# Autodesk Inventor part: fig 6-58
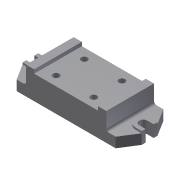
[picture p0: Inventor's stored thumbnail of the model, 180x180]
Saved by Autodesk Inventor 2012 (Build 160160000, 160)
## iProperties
Shininess: 77.0
Angle Display Precision: 2
Document Length Units: 11269
Document Angle Units: 11279
Document Time Units: 11290
Document Mass Units: 11283
Document Length Units Precision: 3
Document Angle Units Precision: 2
Created: 2001-12
Part Number: fig 6-58
Document SubType Name: Modeling
Designer: Renu Muthoo
Density: 1 g/cm^3
Material: Default
Density: 0.0
Volumn: 0.0
Area: 0.0
PropertySet Name: Model Information
Control State: 0
Master: False
Checked Out: False
Author: Renu Muthoo
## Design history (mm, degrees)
sketch "Sketch3"
  geometry: L1 (-59.119, -24.322)-(-59.119, 19.678); L2 (-59.119, 19.678)-(-46.119, 19.678); L3 (-46.119, 19.678)-(-46.119, 13.678); L4 (-46.119, 13.678)-(55.881, 13.678); L5 (55.881, 13.678)-(55.881, 19.678); L6 (55.881, 19.678)-(68.881, 19.678); L7 (68.881, 19.678)-(68.881, -24.322); L8 (68.881, -24.322)-(-59.119, -24.322)
  constraints: 16 end point, 2 equal length
  dimensions: "d10" = 13 distance of L1.end L2.end; "d11" = 102 distance of L3.end L4.end; "d13" = 44 distance between parallel lines of L2 L8; "d14" = 6 distance of L2.end L3.end
extrude "Extrusion1" new body sketch "Sketch3" distance "d15" = 76; taper "d16" = 0 deg
sketch "Sketch4"
  geometry: L1 (0, 0)-(0, 76) reference; L2 (0, 76)-(-15, 76); L3 (-15, 76)-(-31, 50.5); L4 (-31, 50.5)-(-31, 44.5); L5 (-31, 44.5)-(-21, 44.5); L6 (-21, 31.5)-(-31, 31.5); L7 (-31, 31.5)-(-31, 25.5); L8 (-31, 25.5)-(-15, 0); L9 (-15, 0)-(0, 0); L10 (128, 76)-(0, 76) reference; L11 (0, 0)-(128, 0) reference; A1 r 6.5 centre (-21, 38) between (-21, 31.5) and (-21, 44.5)
  constraints: 16 end point, 4 equal length, 3 collinear, 3 parallel, 2 perpendicular, 2 point on circle, 2 tangent, 1 centre point
  dimensions: "d17" = 13 distance between parallel lines of L6 L5; "d18" = 25 distance of L3.end L7.end; "d19" = 10 distance of L6.start L6.end; "d20" = 15 distance of L8.end L1.start; "d21" = 16 horizontal distance of L7.end L8.end
extrude "Extrusion2" join sketch "Sketch4" distance "d22" = 16; taper "d23" = 0 deg
sketch "Sketch5"
  geometry: L1 (-159, 44.5)-(-159, 50.5) reference; L2 (-149, 44.5)-(-159, 44.5) reference; L3 (-159, 31.5)-(-149, 31.5) reference; L4 (-159, 25.5)-(-159, 31.5) reference; L5 (-159, 25.5)-(-149, 25.5); L6 (-149, 50.5)-(-159, 50.5); A1 r 6.5 centre (-149, 38) between (-149, 31.5) and (-149, 44.5) reference; A2 r 12.5 centre (-149, 38) between (-149, 25.5) and (-149, 50.5)
  constraints: 4 end point, 2 point on circle, 2 tangent, 1 centre point, 1 parallel, 1 perpendicular
extrude "Extrusion3" join sketch "Sketch5" distance "d24" = 19; taper "d25" = 0 deg
workplane "Work Plane1"
mirror "Mirror1"
fillet "Fillet1" dims "d27" = 4
sketch "Sketch6"
  geometry: L1 (0, 0)-(0, 76) reference; L2 (0, 0)-(102, 0) reference; 1 further point
  dimensions: "d28" = 20 distance from line of L1 point (20, 15); "d29" = 15 distance from line of L2 point (20, 15)
hole "Hole1" sketch "Sketch6" at (20, 15) diameter "d30" = 10; stored, may be unused: countersink angle "d34" = 82 deg, drill point angle "d36" = 118 deg; dims "d31" = 6, "d32" = 4, "d33" = 2, "d35" = 15
sketch "Sketch7"
  geometry: C1 r 5 at (20, 15) reference; 3 further points
  constraints: 4 other
pattern_linear "Rectangular Pattern2" dims "d45" = 45
body "Solid1"
other parameters: "d26" = -64
